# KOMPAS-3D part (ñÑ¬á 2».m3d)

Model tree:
1. Эскиз:1
2. Операция выдавливания:1
     Расстояние 1 = 0.6
3. Эскиз:2
4. Вырезать элемент выдавливания:1
     Толщина стенки 1 = 3; Толщина стенки 2 = 3; Расстояние 1 = 10
5. Эскиз:3
6. Вырезать элемент выдавливания:2
     Толщина стенки 1 = 3; Толщина стенки 2 = 3; Расстояние 1 = 10
7. Эскиз:4
8. Вырезать элемент выдавливания:3
     Толщина стенки 1 = 3; Толщина стенки 2 = 3; Расстояние 1 = 10
9. Эскиз:5
10. Вырезать элемент выдавливания:4
     Толщина стенки 1 = 3; Толщина стенки 2 = 3; Расстояние 1 = 10
11. Эскиз:6
12. Вырезать элемент выдавливания:5
     Расстояние 1 = 10
